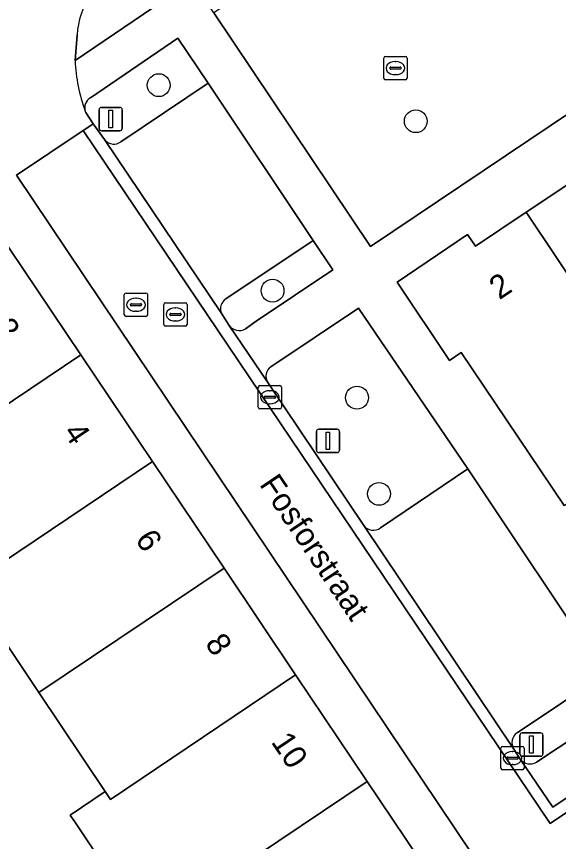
# Model space of a CAD drawing. Extents: x 158793 to 159888, y 384317 to 385256.
# Drawn here: x 159108.92 to 159132.16, y 384528.93 to 384564.3 of the extents above; entities that cross this region are included whole.
import ezdxf

# ---------------------------------------------------------------- set-up
doc = ezdxf.new("R2010")
doc.units = 0
for name, color, linetype in [('IMGEO_Boom', 7, 'Continuous'), ('IMGEO_Erf', 7, 'Continuous'), ('IMGEO_Groenvoorziening', 7, 'Continuous'), ('IMGEO_Kolk', 7, 'Continuous'), ('IMGEO_Lichtmast', 7, 'Continuous'), ('IMGEO_Openbare_ruimte_label', 7, 'Continuous'), ('IMGEO_Pand', 7, 'Continuous'), ('IMGEO_Pand_nummerreeks', 7, 'Continuous'), ('IMGEO_Parkeervlak_open', 7, 'Continuous'), ('IMGEO_Rijbaan_lokaal_open', 7, 'Continuous'), ('IMGEO_Rioolput', 7, 'Continuous'), ('IMGEO_Voetpad_open', 7, 'Continuous')]:
    doc.layers.add(name, color=color, linetype=linetype)

msp = doc.modelspace()

# ---------------------------------------------------------------- linework, layer by layer
at = {"layer": 'IMGEO_Boom'}
for centre in [(159115.016, 384561.354), (159126.036, 384559.809), (159119.897, 384552.544), (159123.516, 384547.957), (159124.46, 384543.835)]:
    msp.add_circle(centre, 0.489, dxfattribs=at)
at = {"layer": 'IMGEO_Erf'}
msp.add_lwpolyline([(159127.802, 384525.792), (159123.956, 384531.511), (159114.509, 384525.165), (159111.442, 384529.73), (159111.219, 384530.062), (159112.722, 384531.071), (159109.879, 384535.313), (159106.814, 384539.886), (159103.748, 384544.459), (159100.683, 384549.032), (159108.605, 384554.36), (159106.711, 384557.186), (159092.403, 384547.537), (159146.803, 384466.42)], dxfattribs=at)
at = {"layer": 'IMGEO_Groenvoorziening'}
msp.add_lwpolyline([(159154.128, 384574.62), (159151.236, 384578.957), (159140.054, 384571.334), (159137.783, 384574.681), (159136.096, 384573.552), (159134.423, 384576.062), (159117.809, 384564.747), (159117.376, 384564.452), (159124.093, 384554.441)], close=True, dxfattribs=at)
for points in [[(159111.514, 384563.514), (159111.43, 384562.409), (159116.454, 384565.827)], [(159117.134, 384561.443), (159115.839, 384563.368), (159112.095, 384560.809)], [(159113.388, 384558.924), (159117.134, 384561.443)], [(159111.868, 384560.239), (159111.893, 384560.178), (159112.208, 384559.697), (159112.692, 384559.025), (159112.706, 384559.008), (159112.72, 384558.992)], [(159122.478, 384553.442), (159121.636, 384554.702), (159117.9, 384552.188)], [(159118.738, 384550.912), (159119.198, 384551.239), (159122.478, 384553.442)], [(159124.522, 384542.38), (159128.263, 384544.902), (159123.582, 384551.801), (159119.826, 384549.287)], [(159117.718, 384551.55), (159117.766, 384551.476), (159118.029, 384551.058)], [(159119.692, 384548.604), (159123.806, 384542.482)], [(159134.145, 384536.107), (159130.383, 384533.591)], [(159131.212, 384532.331), (159134.977, 384534.825), (159134.145, 384536.107)], [(159130.239, 384532.89), (159130.515, 384532.465)]]:
    msp.add_lwpolyline(points, dxfattribs=at)
for centre, radius, start, end in [((159115.418, 384563.215), 3.915, 123.4428, 175.6228), ((159112.322, 384560.389), 0.478, 118.3345, 198.2361), ((159113.092, 384559.329), 0.502, 222.19, 306.185), ((159118.153, 384551.771), 0.488, 121.2425, 206.9141), ((159118.464, 384551.375), 0.538, 216.089, 300.6392), ((159120.101, 384548.878), 0.492, 123.912, 213.8878), ((159124.214, 384542.782), 0.507, 216.345, 307.4396), ((159130.66, 384533.169), 0.505, 123.245, 213.5385), ((159130.939, 384532.788), 0.533, 217.3477, 300.8874)]:
    msp.add_arc(centre, radius, start, end, dxfattribs=at)
at = {"layer": 'IMGEO_Kolk'}
for p, q in [((159119.283, 384547.551), (159119.283, 384548.403)), ((159119.358, 384548.477), (159120.21, 384548.477)), ((159120.284, 384548.403), (159120.284, 384547.551)), ((159119.771, 384548.257), (159119.796, 384548.257)), ((159119.542, 384547.971), (159119.542, 384547.983)), ((159119.98, 384547.934), (159119.582, 384547.934)), ((159119.585, 384548.02), (159119.983, 384548.02)), ((159119.794, 384547.697), (159119.769, 384547.697)), ((159120.026, 384547.983), (159120.026, 384547.971)), ((159120.21, 384547.477), (159119.358, 384547.477)), ((159129.684, 384532.082), (159129.684, 384532.934)), ((159129.759, 384533.008), (159130.611, 384533.008)), ((159130.685, 384532.934), (159130.685, 384532.082)), ((159129.943, 384532.502), (159129.943, 384532.514)), ((159129.986, 384532.551), (159130.384, 384532.551)), ((159130.172, 384532.788), (159130.197, 384532.788)), ((159130.427, 384532.514), (159130.427, 384532.502)), ((159130.381, 384532.465), (159129.983, 384532.465)), ((159130.195, 384532.228), (159130.17, 384532.228)), ((159130.611, 384532.008), (159129.759, 384532.008))]:
    msp.add_line(p, q, dxfattribs=at)
for points in [[(159119.283, 384547.551), (159119.283, 384548.403)], [(159119.358, 384548.477), (159120.21, 384548.477)], [(159120.284, 384548.403), (159120.284, 384547.551)], [(159120.21, 384547.477), (159119.358, 384547.477)], [(159129.684, 384532.082), (159129.684, 384532.934)], [(159129.759, 384533.008), (159130.611, 384533.008)], [(159130.685, 384532.934), (159130.685, 384532.082)], [(159130.611, 384532.008), (159129.759, 384532.008)]]:
    msp.add_lwpolyline(points, dxfattribs=at)
for centre, radius, start, end in [((159119.36, 384548.401), 0.0765, 91.552, 178.448), ((159119.36, 384548.401), 0.0765, 91.552, 178.448), ((159120.208, 384548.401), 0.0765, 1.552, 88.448), ((159120.208, 384548.401), 0.0765, 1.552, 88.448), ((159119.582, 384547.98), 0.0403, 85.8775, 175.7526), ((159119.579, 384547.97), 0.0366, 178.938, 274.7102), ((159119.983, 384547.977), 0.043, 264.8664, 352.4533), ((159119.987, 384547.982), 0.0386, 1.7309, 96.639), ((159119.36, 384547.553), 0.0765, 181.552, 268.448), ((159119.36, 384547.553), 0.0765, 181.552, 268.448), ((159120.208, 384547.553), 0.0765, 271.552, 358.448), ((159120.208, 384547.553), 0.0765, 271.552, 358.448), ((159129.761, 384532.932), 0.0765, 91.552, 178.448), ((159129.761, 384532.932), 0.0765, 91.552, 178.448), ((159130.609, 384532.932), 0.0765, 1.552, 88.448), ((159130.609, 384532.932), 0.0765, 1.552, 88.448), ((159129.983, 384532.511), 0.0403, 85.8775, 175.7526), ((159129.98, 384532.501), 0.0366, 178.938, 274.7102), ((159130.384, 384532.508), 0.043, 264.8664, 352.4533), ((159130.388, 384532.513), 0.0386, 1.7309, 96.639), ((159129.761, 384532.084), 0.0765, 181.552, 268.448), ((159129.761, 384532.084), 0.0765, 181.552, 268.448), ((159130.609, 384532.084), 0.0765, 271.552, 358.448), ((159130.609, 384532.084), 0.0765, 271.552, 358.448)]:
    msp.add_arc(centre, radius, start, end, dxfattribs=at)
for centre, major_axis, ratio, start_param, end_param in [((159119.77, 384547.977), (-0.387, 0.002), 0.722429, 4.712389, 7.853982), ((159119.795, 384547.977), (-0.39, 0.002), 0.717154, 1.570796, 4.712389), ((159130.171, 384532.508), (-0.387, 0.002), 0.722429, 4.712389, 7.853982), ((159130.196, 384532.508), (-0.39, 0.002), 0.717154, 1.570796, 4.712389)]:
    msp.add_ellipse(centre, major_axis=major_axis, ratio=ratio, start_param=start_param, end_param=end_param, dxfattribs=at)
at = {"layer": 'IMGEO_Lichtmast'}
for p, q in [((159112.46, 384559.501), (159112.46, 384560.301)), ((159112.46, 384560.301), (159112.46, 384559.501)), ((159112.56, 384560.401), (159113.35, 384560.401)), ((159113.35, 384560.401), (159112.56, 384560.401)), ((159113.45, 384560.301), (159113.45, 384559.501)), ((159113.45, 384559.501), (159113.45, 384560.301)), ((159113.35, 384559.401), (159112.56, 384559.401)), ((159112.56, 384559.401), (159113.35, 384559.401)), ((159121.775, 384545.706), (159121.775, 384546.506)), ((159121.775, 384546.506), (159121.775, 384545.706)), ((159121.875, 384546.606), (159122.665, 384546.606)), ((159122.665, 384546.606), (159121.875, 384546.606)), ((159122.765, 384546.506), (159122.765, 384545.706)), ((159122.765, 384545.706), (159122.765, 384546.506)), ((159122.665, 384545.606), (159121.875, 384545.606)), ((159121.875, 384545.606), (159122.665, 384545.606)), ((159130.6, 384533.589), (159131.39, 384533.589)), ((159131.39, 384533.589), (159130.6, 384533.589)), ((159130.5, 384532.689), (159130.5, 384533.489)), ((159130.5, 384533.489), (159130.5, 384532.689)), ((159131.49, 384533.489), (159131.49, 384532.689)), ((159131.49, 384532.689), (159131.49, 384533.489)), ((159131.39, 384532.589), (159130.6, 384532.589)), ((159130.6, 384532.589), (159131.39, 384532.589))]:
    msp.add_line(p, q, dxfattribs=at)
for points in [[(159112.88, 384560.276), (159113.03, 384560.276), (159113.03, 384559.526), (159112.88, 384559.526), (159112.88, 384560.276)], [(159122.195, 384546.481), (159122.345, 384546.481), (159122.345, 384545.731), (159122.195, 384545.731), (159122.195, 384546.481)], [(159130.92, 384533.464), (159131.07, 384533.464), (159131.07, 384532.714), (159130.92, 384532.714), (159130.92, 384533.464)]]:
    msp.add_lwpolyline(points, dxfattribs=at)
for centre, start, end in [((159112.56, 384560.301), 90, 180), ((159112.56, 384560.301), 90, 180), ((159113.35, 384560.301), 0, 90), ((159113.35, 384560.301), 360, 90), ((159112.56, 384559.501), 180, 270), ((159112.56, 384559.501), 180, 270), ((159113.35, 384559.501), 270, 0), ((159113.35, 384559.501), 270, 0), ((159121.875, 384546.506), 90, 180), ((159121.875, 384546.506), 90, 180), ((159122.665, 384546.506), 0, 90), ((159122.665, 384546.506), 360, 90), ((159121.875, 384545.706), 180, 270), ((159121.875, 384545.706), 180, 270), ((159122.665, 384545.706), 270, 0), ((159122.665, 384545.706), 270, 0), ((159130.6, 384533.489), 90, 180), ((159130.6, 384533.489), 90, 180), ((159131.39, 384533.489), 0, 90), ((159131.39, 384533.489), 360, 90), ((159130.6, 384532.689), 180, 270), ((159130.6, 384532.689), 180, 270), ((159131.39, 384532.689), 270, 0), ((159131.39, 384532.689), 270, 0)]:
    msp.add_arc(centre, 0.1, start, end, dxfattribs=at)
at = {"layer": 'IMGEO_Pand'}
for points in [[(159134.907, 384559.415), (159132.605, 384557.865), (159132.946, 384557.359), (159130.769, 384555.904), (159136.089, 384547.966), (159136.282, 384548.095), (159140.37, 384550.832), (159140.57, 384550.966)], [(159130.769, 384555.904), (159128.592, 384554.449), (159128.249, 384554.954), (159125.243, 384552.911), (159127.488, 384549.552), (159127.991, 384549.889), (159132.401, 384543.329), (159137.097, 384546.463), (159137.289, 384546.591), (159136.282, 384548.095), (159136.089, 384547.966)], [(159111.676, 384549.79), (159108.605, 384554.36), (159100.683, 384549.032), (159103.748, 384544.459)], [(159114.746, 384545.22), (159111.676, 384549.79), (159103.748, 384544.459), (159106.814, 384539.886)], [(159117.816, 384540.65), (159114.746, 384545.22), (159106.814, 384539.886), (159109.879, 384535.313)], [(159120.886, 384536.081), (159117.816, 384540.65), (159109.879, 384535.313), (159112.722, 384531.071), (159112.944, 384530.74)], [(159123.956, 384531.511), (159120.886, 384536.081), (159112.944, 384530.74), (159112.722, 384531.071), (159111.219, 384530.062), (159111.442, 384529.73), (159114.509, 384525.165)]]:
    msp.add_lwpolyline(points, close=True, dxfattribs=at)
at = {"layer": 'IMGEO_Parkeervlak_open'}
for points in [[(159117.134, 384561.443), (159113.388, 384558.924)], [(159117.9, 384552.188), (159121.636, 384554.702), (159117.134, 384561.443)], [(159112.72, 384558.992), (159112.706, 384559.008), (159112.692, 384559.025), (159117.718, 384551.55)], [(159128.263, 384544.902), (159124.522, 384542.38)], [(159130.383, 384533.591), (159134.145, 384536.107), (159128.263, 384544.902)], [(159123.806, 384542.482), (159130.239, 384532.89)]]:
    msp.add_lwpolyline(points, dxfattribs=at)
for centre, radius, start, end in [((159113.092, 384559.329), 0.502, 222.19, 306.185), ((159118.153, 384551.771), 0.488, 121.2425, 206.9141), ((159124.214, 384542.782), 0.507, 216.345, 307.4396), ((159130.66, 384533.169), 0.505, 123.245, 213.5385)]:
    msp.add_arc(centre, radius, start, end, dxfattribs=at)
at = {"layer": 'IMGEO_Rijbaan_lokaal_open'}
msp.add_lwpolyline([(159119.692, 384548.604), (159118.029, 384551.058), (159117.766, 384551.476), (159117.718, 384551.55), (159112.692, 384559.025), (159112.208, 384559.697), (159111.807, 384559.428), (159111.782, 384559.411), (159131.797, 384529.704), (159178.017, 384560.678), (159195.001, 384572.021), (159194.721, 384572.428), (159177.742, 384561.091), (159131.92, 384530.403), (159130.515, 384532.465), (159130.239, 384532.89), (159123.806, 384542.482)], close=True, dxfattribs=at)
for points in [[(159211.83, 384541.696), (159201.909, 384535.023), (159197.999, 384532.399), (159196.883, 384531.677), (159196.033, 384531.127), (159195.59, 384530.821), (159178.371, 384556.579), (159178.788, 384556.84), (159178.669, 384557.017), (159179.615, 384557.65), (159184.571, 384560.964), (159188.261, 384563.455), (159191.903, 384565.914), (159196.883, 384569.224), (159195.001, 384572.021), (159178.017, 384560.678), (159131.797, 384529.704), (159111.782, 384559.411), (159108.917, 384557.49), (159163.183, 384476.655), (159166.119, 384478.572), (159153.048, 384498.068), (159198.654, 384528.669), (159243.562, 384558.734)], [(159111.43, 384562.409), (159111.514, 384563.514)], [(159108.917, 384557.49), (159111.782, 384559.411), (159111.807, 384559.428), (159112.208, 384559.697), (159111.893, 384560.178), (159111.868, 384560.239)]]:
    msp.add_lwpolyline(points, dxfattribs=at)
for centre, radius, start, end in [((159115.418, 384563.215), 3.915, 123.4428, 175.6228), ((159118.433, 384562.693), 7.009, 182.3252, 200.4977)]:
    msp.add_arc(centre, radius, start, end, dxfattribs=at)
at = {"layer": 'IMGEO_Rioolput'}
for p, q in [((159124.739, 384562.585), (159125.591, 384562.585)), ((159124.664, 384561.659), (159124.664, 384562.511)), ((159125.152, 384562.365), (159125.177, 384562.365)), ((159125.665, 384562.511), (159125.665, 384561.659)), ((159124.923, 384562.079), (159124.923, 384562.091)), ((159125.361, 384562.042), (159124.963, 384562.042)), ((159124.966, 384562.128), (159125.364, 384562.128)), ((159125.407, 384562.091), (159125.407, 384562.079)), ((159125.591, 384561.585), (159124.739, 384561.585)), ((159125.175, 384561.805), (159125.15, 384561.805)), ((159113.54, 384551.516), (159113.54, 384552.368)), ((159113.615, 384552.442), (159114.467, 384552.442)), ((159114.541, 384552.368), (159114.541, 384551.516)), ((159113.799, 384551.936), (159113.799, 384551.948)), ((159113.842, 384551.985), (159114.24, 384551.985)), ((159114.028, 384552.222), (159114.053, 384552.222)), ((159114.283, 384551.948), (159114.283, 384551.936)), ((159115.231, 384551.101), (159115.231, 384551.953)), ((159115.306, 384552.027), (159116.158, 384552.027)), ((159116.232, 384551.953), (159116.232, 384551.101)), ((159114.237, 384551.899), (159113.839, 384551.899)), ((159114.051, 384551.662), (159114.026, 384551.662)), ((159115.719, 384551.807), (159115.744, 384551.807)), ((159114.467, 384551.442), (159113.615, 384551.442)), ((159115.49, 384551.521), (159115.49, 384551.533)), ((159115.928, 384551.484), (159115.53, 384551.484)), ((159115.533, 384551.57), (159115.931, 384551.57)), ((159115.742, 384551.247), (159115.717, 384551.247)), ((159115.974, 384551.533), (159115.974, 384551.521)), ((159116.158, 384551.027), (159115.306, 384551.027))]:
    msp.add_line(p, q, dxfattribs=at)
for points in [[(159124.739, 384562.585), (159125.591, 384562.585)], [(159124.664, 384561.659), (159124.664, 384562.511)], [(159125.665, 384562.511), (159125.665, 384561.659)], [(159125.591, 384561.585), (159124.739, 384561.585)], [(159113.54, 384551.516), (159113.54, 384552.368)], [(159113.615, 384552.442), (159114.467, 384552.442)], [(159114.541, 384552.368), (159114.541, 384551.516)], [(159115.231, 384551.101), (159115.231, 384551.953)], [(159115.306, 384552.027), (159116.158, 384552.027)], [(159116.232, 384551.953), (159116.232, 384551.101)], [(159114.467, 384551.442), (159113.615, 384551.442)], [(159116.158, 384551.027), (159115.306, 384551.027)]]:
    msp.add_lwpolyline(points, dxfattribs=at)
for centre, radius, start, end in [((159124.741, 384562.509), 0.0765, 91.552, 178.448), ((159124.741, 384562.509), 0.0765, 91.552, 178.448), ((159125.589, 384562.509), 0.0765, 1.552, 88.448), ((159125.589, 384562.509), 0.0765, 1.552, 88.448), ((159124.963, 384562.088), 0.0403, 85.8775, 175.7526), ((159124.96, 384562.078), 0.0366, 178.938, 274.7102), ((159125.364, 384562.085), 0.043, 264.8664, 352.4533), ((159125.368, 384562.09), 0.0386, 1.7309, 96.639), ((159124.741, 384561.661), 0.0765, 181.552, 268.448), ((159124.741, 384561.661), 0.0765, 181.552, 268.448), ((159125.589, 384561.661), 0.0765, 271.552, 358.448), ((159125.589, 384561.661), 0.0765, 271.552, 358.448), ((159113.617, 384552.366), 0.0765, 91.552, 178.448), ((159113.617, 384552.366), 0.0765, 91.552, 178.448), ((159114.465, 384552.366), 0.0765, 1.552, 88.448), ((159114.465, 384552.366), 0.0765, 1.552, 88.448), ((159113.839, 384551.945), 0.0403, 85.8775, 175.7526), ((159114.244, 384551.947), 0.0386, 1.7309, 96.639), ((159115.308, 384551.951), 0.0765, 91.552, 178.448), ((159115.308, 384551.951), 0.0765, 91.552, 178.448), ((159116.156, 384551.951), 0.0765, 1.552, 88.448), ((159116.156, 384551.951), 0.0765, 1.552, 88.448), ((159113.836, 384551.935), 0.0366, 178.938, 274.7102), ((159114.24, 384551.942), 0.043, 264.8664, 352.4533), ((159113.617, 384551.518), 0.0765, 181.552, 268.448), ((159113.617, 384551.518), 0.0765, 181.552, 268.448), ((159114.465, 384551.518), 0.0765, 271.552, 358.448), ((159114.465, 384551.518), 0.0765, 271.552, 358.448), ((159115.53, 384551.53), 0.0403, 85.8775, 175.7526), ((159115.527, 384551.52), 0.0366, 178.938, 274.7102), ((159115.931, 384551.527), 0.043, 264.8664, 352.4533), ((159115.935, 384551.532), 0.0386, 1.7309, 96.639), ((159115.308, 384551.103), 0.0765, 181.552, 268.448), ((159115.308, 384551.103), 0.0765, 181.552, 268.448), ((159116.156, 384551.103), 0.0765, 271.552, 358.448), ((159116.156, 384551.103), 0.0765, 271.552, 358.448)]:
    msp.add_arc(centre, radius, start, end, dxfattribs=at)
for centre, major_axis, ratio, start_param, end_param in [((159125.151, 384562.085), (-0.387, 0.002), 0.722429, 4.712389, 7.853982), ((159125.176, 384562.085), (-0.39, 0.002), 0.717154, 1.570796, 4.712389), ((159114.027, 384551.942), (-0.387, 0.002), 0.722429, 4.712389, 7.853982), ((159114.052, 384551.942), (-0.39, 0.002), 0.717154, 1.570796, 4.712389), ((159115.718, 384551.527), (-0.387, 0.002), 0.722429, 4.712389, 7.853982), ((159115.743, 384551.527), (-0.39, 0.002), 0.717154, 1.570796, 4.712389)]:
    msp.add_ellipse(centre, major_axis=major_axis, ratio=ratio, start_param=start_param, end_param=end_param, dxfattribs=at)
at = {"layer": 'IMGEO_Voetpad_open'}
for points in [[(159177.742, 384561.091), (159194.721, 384572.428), (159194.349, 384572.964), (159193.8, 384573.756), (159193.655, 384573.965), (159190.856, 384572.121), (159189.399, 384571.161), (159176.47, 384562.598), (159175.007, 384561.62), (159171.232, 384567.261), (159162.529, 384580.264), (159155.852, 384575.778), (159154.128, 384574.62), (159124.093, 384554.441), (159117.376, 384564.452), (159116.454, 384565.827), (159111.43, 384562.409)], [(159112.095, 384560.809), (159115.839, 384563.368), (159117.134, 384561.443), (159121.636, 384554.702), (159122.478, 384553.442), (159119.198, 384551.239), (159118.738, 384550.912)], [(159130.515, 384532.465), (159131.92, 384530.403), (159177.742, 384561.091)], [(159163.183, 384476.655), (159108.917, 384557.49)], [(159132.401, 384543.329), (159127.991, 384549.889), (159127.488, 384549.552), (159125.243, 384552.911), (159128.249, 384554.954), (159128.592, 384554.449), (159130.769, 384555.904), (159132.946, 384557.359)], [(159106.711, 384557.186), (159108.605, 384554.36), (159111.676, 384549.79), (159114.746, 384545.22), (159117.816, 384540.65), (159120.886, 384536.081), (159123.956, 384531.511), (159127.802, 384525.792), (159130.881, 384521.199), (159133.961, 384516.607)], [(159119.826, 384549.287), (159123.582, 384551.801), (159128.263, 384544.902), (159134.145, 384536.107), (159134.977, 384534.825), (159131.212, 384532.331)], [(159118.029, 384551.058), (159119.692, 384548.604)]]:
    msp.add_lwpolyline(points, dxfattribs=at)
for centre, radius, start, end in [((159118.433, 384562.693), 7.009, 182.3252, 200.4977), ((159112.322, 384560.389), 0.478, 118.3345, 198.2361), ((159118.464, 384551.375), 0.538, 216.089, 300.6392), ((159120.101, 384548.878), 0.492, 123.912, 213.8878), ((159130.939, 384532.788), 0.533, 217.3477, 300.8874)]:
    msp.add_arc(centre, radius, start, end, dxfattribs=at)

# ---------------------------------------------------------------- texts
at = {"layer": 'IMGEO_Openbare_ruimte_label'}
msp.add_text('Fosforstraat', height=1, rotation=303.9125, dxfattribs=at).set_placement((159119.306, 384544.24))
at = {"layer": 'IMGEO_Pand_nummerreeks'}
for s, rotation, p in [('2', 33.7587, (159129.621, 384552.13)), ('2', 303.8937, (159107.882, 384550.954)), ('4', 303.8937, (159110.893, 384546.472)), ('6', 303.8937, (159113.978, 384541.88)), ('8', 303.896, (159116.974, 384537.42)), ('10', 303.8902, (159119.809, 384533.201))]:
    msp.add_text(s, height=1, rotation=rotation, dxfattribs=at).set_placement(p)

doc.saveas('drawing.dxf')
